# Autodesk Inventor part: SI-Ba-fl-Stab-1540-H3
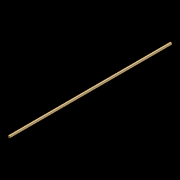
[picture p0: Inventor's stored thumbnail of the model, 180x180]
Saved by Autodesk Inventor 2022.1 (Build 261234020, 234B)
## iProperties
Part Number: SI-Ba-fl-Stab-1540-H3
Material: Allgemein
Document SubType Name: Modellieren
Designer: joachim
Appearance: Vorgabe
Author: joachim
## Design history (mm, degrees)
sketch "Skizze1"
  geometry: L1 (0, 0)-(15, 0); L2 (15, 0)-(15, 15); L3 (15, 15)-(0, 15); L4 (0, 15)-(0, 0)
  constraints: 8 end point, 2 parallel, 1 horizontal, 1 perpendicular
  dimensions: "d0" = 15 distance of L3.end L2.end; "d1" = 15 distance of L2.end L1.end
extrude "Extrusion1" new body sketch "Skizze1" distance "d2" = 1540; taper "d3" = 0 deg
node "Volumenkörper1"
node "Volumenkörper"
node "Flächenkörper"
